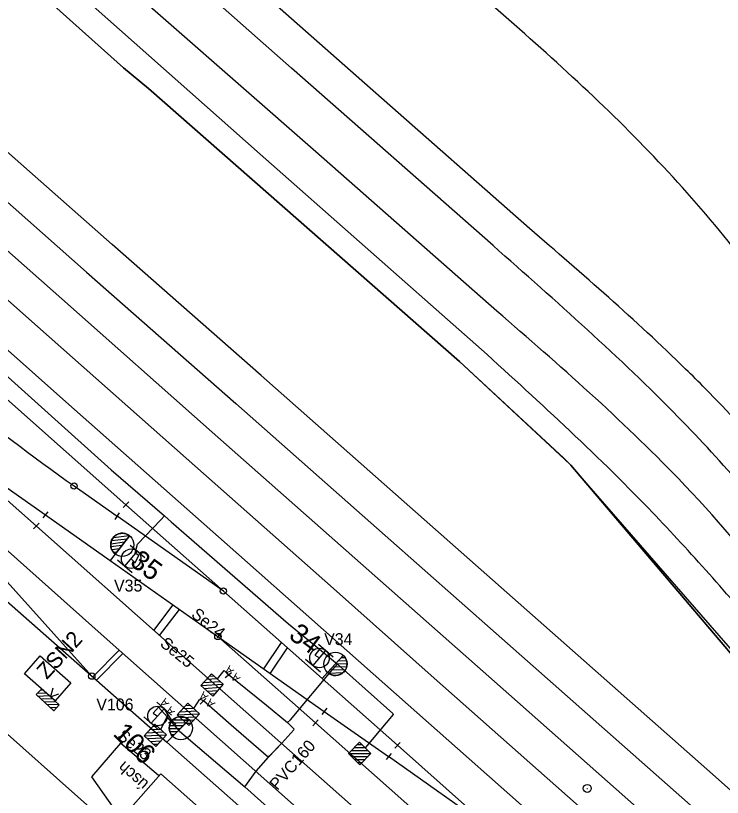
# Model space of a CAD drawing. Extents: x -496570 to -495506, y -1089156 to -1088046.
# Drawn here: x -496185.7 to -496096.7, y -1088491.2 to -1088392.7 of the extents above; entities that cross this region are included whole.
import ezdxf

# ---------------------------------------------------------------- set-up
doc = ezdxf.new("R2010")
doc.units = 0
for name, color, linetype in [('11', 7, 'Continuous'), ('14', 7, 'Continuous'), ('15', 7, 'Continuous'), ('20', 7, 'Continuous'), ('27', 7, 'Continuous'), ('39', 7, 'Continuous'), ('54', 7, 'Continuous'), ('PŘÍSTUPOVÉ_CESTY', 7, 'Continuous'), ('PŮVODNÍ_NÁVRH', 7, 'Continuous'), ('SEE', 7, 'Continuous')]:
    doc.layers.add(name, color=color, linetype=linetype)

msp = doc.modelspace()

# ---------------------------------------------------------------- linework, layer by layer
at = {"layer": '11'}
for p, q in [((-496175.966, -1088476.01), (-496172.647, -1088472.653)), ((-496175.563, -1088476.455), (-496172.198, -1088473.051)), ((-496113.753, -1088490.122), (-496113.653, -1088490.122))]:
    msp.add_line(p, q, dxfattribs=at)
for points in [[(-496168.336, -1088470.189), (-496165.878, -1088466.959)], [(-496167.583, -1088470.852), (-496165.082, -1088467.565)], [(-496154.451, -1088475.041), (-496152.237, -1088471.722)], [(-496153.619, -1088475.595), (-496151.481, -1088472.391)]]:
    msp.add_lwpolyline(points, dxfattribs=at)
msp.add_circle((-496113.703, -1088490.122), 0.5, dxfattribs=at)
at = {"layer": '14'}
for p, q in [((-496178.376, -1088451.975), (-496172.957, -1088455.79)), ((-496181.983, -1088455.616), (-496173.824, -1088461.376)), ((-496137.6, -1088484.685), (-496147.124, -1088476.255)), ((-496146.847, -1088480.405), (-496138.739, -1088486.107))]:
    msp.add_line(p, q, dxfattribs=at)
for points in [[(-496500.326, -1088150.883), (-496478.319, -1088170.391), (-496459.205, -1088187.309), (-496440.603, -1088203.768), (-496419.398, -1088222.532), (-496401.337, -1088238.524), (-496381.863, -1088255.763), (-496363.496, -1088272.022), (-496344.908, -1088288.479), (-496325.602, -1088305.577), (-496305.115, -1088323.698), (-496285.279, -1088341.274), (-496267.778, -1088356.78), (-496248.642, -1088373.733), (-496220.391, -1088398.759), (-496201.351, -1088415.62), (-496182.974, -1088431.889), (-496164.259, -1088448.462), (-496145.687, -1088464.902), (-496132.984, -1088476.226), (-496115.09, -1088492.058), (-496092.682, -1088511.89), (-496073.961, -1088528.378)], [(-496111.45, -1088501.61), (-496112.796, -1088500.414), (-496116.847, -1088496.777), (-496137.726, -1088478.277), (-496158.004, -1088460.314), (-496179.39, -1088441.364), (-496198.571, -1088424.361), (-496223.52, -1088402.267), (-496247.329, -1088381.198), (-496269.626, -1088361.454), (-496288.304, -1088344.927), (-496319.947, -1088316.905), (-496344.485, -1088295.207), (-496348.139, -1088291.966), (-496366.841, -1088275.405), (-496385.169, -1088259.187), (-496404.395, -1088242.153), (-496422.154, -1088226.434), (-496443.818, -1088207.26), (-496462.548, -1088190.678), (-496481.576, -1088173.849), (-496503.417, -1088154.088)], [(-496036.118, -1088555.5), (-496048.975, -1088544.1), (-496066.196, -1088528.906), (-496086.152, -1088511.349), (-496104.929, -1088494.746), (-496123.588, -1088478.229), (-496142.293, -1088461.701), (-496160.965, -1088445.175), (-496179.891, -1088428.396), (-496198.214, -1088412.189), (-496217.292, -1088395.311), (-496245.811, -1088370.064), (-496264.918, -1088353.145), (-496281.988, -1088338.018), (-496302.247, -1088320.079), (-496322.57, -1088302.076), (-496341.966, -1088284.907), (-496360.552, -1088268.447), (-496378.713, -1088252.378), (-496398.4, -1088234.928), (-496416.447, -1088218.945), (-496437.668, -1088200.162), (-496456.103, -1088183.845), (-496474.042, -1088168.071)], [(-496082.486, -1088502.043), (-496098.63, -1088487.696), (-496117.358, -1088471.138), (-496136.056, -1088454.602), (-496154.785, -1088438.063), (-496173.551, -1088421.521), (-496192.303, -1088405.013), (-496211.05, -1088388.494), (-496229.814, -1088371.969), (-496241.71, -1088361.483), (-496259.312, -1088345.98), (-496335.952, -1088278.18), (-496354.664, -1088261.608), (-496372.853, -1088245.502), (-496392.083, -1088228.459), (-496410.817, -1088211.882), (-496431.795, -1088193.31), (-496448.334, -1088178.663)], [(-496419.776, -1088210.17), (-496413.73, -1088215.561), (-496395.384, -1088231.799), (-496375.938, -1088249.024), (-496357.661, -1088265.193), (-496339.088, -1088281.642), (-496320.817, -1088297.785), (-496278.447, -1088335.251), (-496262.212, -1088349.594), (-496242.734, -1088366.795), (-496214.147, -1088392.048), (-496195.339, -1088408.643), (-496176.8, -1088425.002), (-496157.997, -1088441.59), (-496139.148, -1088458.239), (-496120.509, -1088474.69), (-496101.775, -1088491.246), (-496088.913, -1088502.664), (-496081.326, -1088509.353), (-496072.768, -1088516.905)], [(-496120.979, -1088419.513), (-496140.339, -1088402.432), (-496221.525, -1088330.811), (-496231.876, -1088321.658)], [(-496125.575, -1088421.675), (-496150.959, -1088399.291), (-496155.261, -1088395.496), (-496219.317, -1088338.861)], [(-496125.082, -1088429.936), (-496147.897, -1088409.846), (-496175.915, -1088385.245), (-496200.868, -1088363.307), (-496213.622, -1088352.053), (-496223.062, -1088343.696)], [(-496128.434, -1088433.508), (-496154.903, -1088410.124), (-496191.894, -1088377.361), (-496213.869, -1088358.021), (-496226.145, -1088347.189)], [(-496174.593, -1088471.013), (-496192.559, -1088454.988), (-496206.347, -1088442.759), (-496213.463, -1088436.447), (-496216.342, -1088433.89), (-496225.123, -1088426.139), (-496237.731, -1088415.01), (-496248.348, -1088406.17), (-496261.601, -1088395.991)], [(-496235.541, -1088397.911), (-496201.57, -1088427.952), (-496171.826, -1088454.349)], [(-496183.115, -1088457.032), (-496166.27, -1088472.019), (-496131.046, -1088503.215), (-496098.048, -1088532.397), (-496093.805, -1088536.044)], [(-496093.621, -1088542.853), (-496114.06, -1088524.717), (-496138.8, -1088502.766), (-496174.593, -1088471.013)], [(-496173.425, -1088495.115), (-496178.653, -1088490.5), (-496194.892, -1088476.055)], [(-496147.947, -1088481.853), (-496126.772, -1088500.653), (-496102.22, -1088522.373)], [(-496104.138, -1088539.66), (-496119.75, -1088525.847), (-496148.539, -1088500.347), (-496166.679, -1088484.292)]]:
    msp.add_lwpolyline(points, dxfattribs=at)
msp.add_circle((-496178.376, -1088451.975), 0.4, dxfattribs=at)
msp.add_ellipse((-495933.646, -1088110.004), major_axis=(-336.539, 253.741), ratio=0.997726, start_param=1.503783, end_param=1.595629, dxfattribs=at)
for points in [[(-496074.283, -1088455.273), (-496090.055, -1088428.91), (-496108.418, -1088407.261), (-496129.685, -1088387.877)], [(-496060.305, -1088494.392), (-496069.107, -1088478.342), (-496082.819, -1088457.845), (-496098.833, -1088439.695), (-496101.304, -1088437.234), (-496120.979, -1088419.513)], [(-496072.447, -1088480.385), (-496086.263, -1088461.553), (-496102.223, -1088443.302), (-496125.575, -1088421.675)], [(-496074.345, -1088485.622), (-496089.123, -1088466.132), (-496102.218, -1088451.049), (-496125.082, -1088429.936)], [(-496077.528, -1088487.052), (-496084.13, -1088479.499), (-496092.21, -1088470.077), (-496106.458, -1088454.308), (-496128.434, -1088433.508)]]:
    msp.add_spline(points, degree=3, dxfattribs=at)
at = {"layer": '15'}
for p, q in [((-496171.312, -1088459.424), (-496169.434, -1088461.018)), ((-496171.967, -1088462.099), (-496170.373, -1088460.221)), ((-496172.906, -1088461.302), (-496171.028, -1088462.896)), ((-496147.582, -1088471.933), (-496145.713, -1088473.538)), ((-496148.253, -1088474.605), (-496146.647, -1088472.735)), ((-496149.187, -1088473.802), (-496147.318, -1088475.407)), ((-496161.681, -1088476.352), (-496160.356, -1088476.27)), ((-496161.33, -1088475.955), (-496160.753, -1088475.919)), ((-496162.383, -1088477.148), (-496159.56, -1088476.972)), ((-496162.033, -1088476.75), (-496159.958, -1088476.621)), ((-496161.986, -1088477.498), (-496159.911, -1088477.369)), ((-496161.588, -1088477.85), (-496160.262, -1088477.767)), ((-496161.191, -1088478.2), (-496160.613, -1088478.165)), ((-496167.95, -1088479.251), (-496166.111, -1088480.89)), ((-496168.67, -1088481.91), (-496167.03, -1088480.07)), ((-496164.662, -1088480.054), (-496163.335, -1088479.989)), ((-496164.306, -1088479.661), (-496163.728, -1088479.633)), ((-496169.589, -1088481.09), (-496167.75, -1088482.729)), ((-496165.374, -1088480.84), (-496162.549, -1088480.702)), ((-496165.018, -1088480.447), (-496162.942, -1088480.346)), ((-496164.982, -1088481.196), (-496162.905, -1088481.094)), ((-496168.464, -1088482.306), (-496167.886, -1088482.281)), ((-496164.588, -1088481.553), (-496163.262, -1088481.488)), ((-496164.196, -1088481.909), (-496163.618, -1088481.88)), ((-496169.18, -1088483.089), (-496167.103, -1088482.997)), ((-496168.822, -1088482.697), (-496167.495, -1088482.639)), ((-496169.538, -1088483.479), (-496166.713, -1088483.355)), ((-496169.147, -1088483.837), (-496167.071, -1088483.746)), ((-496168.756, -1088484.196), (-496167.429, -1088484.138)), ((-496168.365, -1088484.554), (-496167.787, -1088484.529)), ((-496143.041, -1088484.968), (-496141.713, -1088484.957)), ((-496142.67, -1088484.59), (-496142.091, -1088484.586)), ((-496143.785, -1088485.725), (-496140.957, -1088485.701)), ((-496143.414, -1088485.347), (-496141.335, -1088485.33)), ((-496143.407, -1088486.097), (-496141.329, -1088486.079)), ((-496143.029, -1088486.469), (-496141.701, -1088486.458)), ((-496142.651, -1088486.84), (-496142.072, -1088486.836))]:
    msp.add_line(p, q, dxfattribs=at)
for points in [[(-496161.06, -1088475.648), (-496159.56, -1088476.972), (-496160.884, -1088478.471), (-496162.383, -1088477.148)], [(-496161.06, -1088475.648), (-496159.56, -1088476.972), (-496160.884, -1088478.471), (-496162.383, -1088477.148)], [(-496164.031, -1088479.358), (-496162.549, -1088480.702), (-496163.893, -1088482.183), (-496165.374, -1088480.84)], [(-496164.031, -1088479.358), (-496162.549, -1088480.702), (-496163.893, -1088482.183), (-496165.374, -1088480.84)], [(-496168.187, -1088482.005), (-496166.713, -1088483.355), (-496168.063, -1088484.83), (-496169.538, -1088483.479)], [(-496168.187, -1088482.005), (-496166.713, -1088483.355), (-496168.063, -1088484.83), (-496169.538, -1088483.479)], [(-496142.383, -1088484.299), (-496140.957, -1088485.701), (-496142.359, -1088487.127), (-496143.785, -1088485.725)], [(-496142.383, -1088484.299), (-496140.957, -1088485.701), (-496142.359, -1088487.127), (-496143.785, -1088485.725)]]:
    msp.add_lwpolyline(points, close=True, dxfattribs=at)
for points in [[(-496161.06, -1088475.648), (-496159.56, -1088476.972), (-496160.884, -1088478.471), (-496162.383, -1088477.148), (-496161.06, -1088475.648)], [(-496161.06, -1088475.648), (-496159.56, -1088476.972), (-496160.884, -1088478.471), (-496162.383, -1088477.148), (-496161.06, -1088475.648)], [(-496164.031, -1088479.358), (-496162.549, -1088480.702), (-496163.893, -1088482.183), (-496165.374, -1088480.84), (-496164.031, -1088479.358)], [(-496164.031, -1088479.358), (-496162.549, -1088480.702), (-496163.893, -1088482.183), (-496165.374, -1088480.84), (-496164.031, -1088479.358)], [(-496168.187, -1088482.005), (-496166.713, -1088483.355), (-496168.063, -1088484.83), (-496169.538, -1088483.479), (-496168.187, -1088482.005)], [(-496168.187, -1088482.005), (-496166.713, -1088483.355), (-496168.063, -1088484.83), (-496169.538, -1088483.479), (-496168.187, -1088482.005)], [(-496142.383, -1088484.299), (-496140.957, -1088485.701), (-496142.359, -1088487.127), (-496143.785, -1088485.725), (-496142.383, -1088484.299)], [(-496142.383, -1088484.299), (-496140.957, -1088485.701), (-496142.359, -1088487.127), (-496143.785, -1088485.725), (-496142.383, -1088484.299)]]:
    msp.add_lwpolyline(points, dxfattribs=at)
for centre in [(-496171.168, -1088461.155), (-496147.448, -1088473.665), (-496167.848, -1088480.986)]:
    msp.add_circle(centre, 1.232, dxfattribs=at)
at = {"layer": '20'}
for p, q in [((-496158.548, -1088475.526), (-496159.308, -1088476.174)), ((-496161.763, -1088478.788), (-496162.483, -1088479.482)), ((-496167.155, -1088479.93), (-496166.06, -1088481.58)), ((-496166.477, -1088481.857), (-496165.643, -1088481.303))]:
    msp.add_line(p, q, dxfattribs=at)
at = {"layer": '27'}
for p, q in [((-496171.474, -1088453.994), (-496172.178, -1088454.704)), ((-496181.669, -1088455.227), (-496182.297, -1088456.005)), ((-496172.69, -1088455.367), (-496173.224, -1088456.213)), ((-496182.768, -1088456.672), (-496183.462, -1088457.392)), ((-496173.659, -1088458.874), (-496171.692, -1088458.624)), ((-496173.421, -1088458.47), (-496171.429, -1088458.218)), ((-496171.403, -1088458.247), (-496173.195, -1088460.561)), ((-496171.396, -1088458.242), (-496173.189, -1088460.555)), ((-496172.762, -1088458.014), (-496172.175, -1088457.94)), ((-496171.397, -1088458.241), (-496171.396, -1088458.242)), ((-496173.748, -1088459.258), (-496172.013, -1088459.038)), ((-496173.734, -1088459.629), (-496172.334, -1088459.451)), ((-496173.197, -1088460.561), (-496173.824, -1088461.376)), ((-496173.627, -1088459.989), (-496172.654, -1088459.865)), ((-496173.413, -1088460.334), (-496172.975, -1088460.279)), ((-496146.428, -1088475.497), (-496144.442, -1088473.347)), ((-496144.442, -1088473.347), (-496146.427, -1088475.498)), ((-496145.419, -1088474.406), (-496143.976, -1088474.349)), ((-496145.06, -1088474.017), (-496144.045, -1088473.976)), ((-496144.699, -1088473.627), (-496144.223, -1088473.608)), ((-496146.14, -1088475.185), (-496144.143, -1088475.105)), ((-496145.78, -1088474.795), (-496144.005, -1088474.725)), ((-496146.429, -1088475.498), (-496147.124, -1088476.255)), ((-496146.427, -1088475.498), (-496146.428, -1088475.497)), ((-496146.34, -1088475.568), (-496144.443, -1088475.493)), ((-496146.537, -1088480.012), (-496147.157, -1088480.798)), ((-496165.21, -1088481.087), (-496164.619, -1088481.085)), ((-496166.342, -1088482.199), (-496164.594, -1088482.195)), ((-496166.207, -1088481.829), (-496164.224, -1088481.824)), ((-496163.891, -1088481.486), (-496165.955, -1088483.561)), ((-496163.883, -1088481.481), (-496165.948, -1088483.555)), ((-496165.921, -1088481.458), (-496163.913, -1088481.453)), ((-496163.884, -1088481.48), (-496163.883, -1088481.481)), ((-496147.604, -1088481.489), (-496148.29, -1088482.217)), ((-496166.375, -1088482.569), (-496164.963, -1088482.566)), ((-496166.313, -1088482.94), (-496165.332, -1088482.936)), ((-496165.956, -1088483.561), (-496166.679, -1088484.292)), ((-496166.143, -1088483.309), (-496165.702, -1088483.308)), ((-496137.261, -1088484.318), (-496137.939, -1088485.052)), ((-496138.42, -1088485.722), (-496139.058, -1088486.492))]:
    msp.add_line(p, q, dxfattribs=at)
for points in [[(-496183.115, -1088457.032), (-496195.371, -1088446.182), (-496207.812, -1088435.168)], [(-496195.371, -1088446.182), (-496181.983, -1088455.616)], [(-496147.124, -1088476.255), (-496159.556, -1088465.23), (-496171.826, -1088454.349)], [(-496159.556, -1088465.23), (-496172.957, -1088455.79)], [(-496173.824, -1088461.376), (-496160.246, -1088470.954), (-496146.847, -1088480.405)], [(-496176.139, -1088475.956), (-496187.184, -1088463.633)], [(-496187.97, -1088465.532), (-496166.679, -1088484.292)], [(-496160.246, -1088470.954), (-496147.947, -1088481.853)], [(-496112.903, -1088506.6), (-496125.331, -1088495.572), (-496137.6, -1088484.685)], [(-496125.331, -1088495.572), (-496138.739, -1088486.107)]]:
    msp.add_lwpolyline(points, dxfattribs=at)
for centre, radius in [((-496172.293, -1088459.399), 1.462), ((-496159.556, -1088465.23), 0.4), ((-496160.246, -1088470.954), 0.4), ((-496145.428, -1088474.417), 1.462), ((-496176.139, -1088475.956), 0.4), ((-496164.916, -1088482.518), 1.462)]:
    msp.add_circle(centre, radius, dxfattribs=at)
for centre, start, end in [((-496172.292, -1088459.398), 52.25556, 232.21641), ((-496145.435, -1088474.422), 227.29698, 47.25783), ((-496164.915, -1088482.518), 45.17373, 225.13458)]:
    msp.add_arc(centre, 1.464, start, end, dxfattribs=at)
at = {"layer": '39'}
for points in [[(-496182.631, -1088473.407), (-496178.781, -1088476.82), (-496180.757, -1088479.091), (-496184.629, -1088475.67), (-496182.631, -1088473.407)], [(-496172.423, -1088493.891), (-496176.128, -1088488.669), (-496172.468, -1088484.41), (-496167.748, -1088488.466)], [(-496122.209, -1088528.323), (-496134.209, -1088541.938), (-496150.053, -1088527.973), (-496152.367, -1088530.599), (-496181.619, -1088504.378), (-496167.429, -1088488.299), (-496122.209, -1088528.323)]]:
    msp.add_lwpolyline(points, dxfattribs=at)
at = {"layer": '54'}
for p, q in [((-496159.11, -1088475.58), (-496158.928, -1088475.85)), ((-496162.06, -1088479.04), (-496162.123, -1088479.135))]:
    msp.add_line(p, q, dxfattribs=at)
for points in [[(-496093.74, -1088475.27), (-496115.78, -1088449.34), (-496116.666, -1088448.476), (-496129.8, -1088436.28), (-496168.994, -1088401.872), (-496172.14, -1088399.257), (-496208.919, -1088366.316), (-496218.168, -1088358.05), (-496219.89, -1088357.07), (-496220.84, -1088356.616), (-496221.139, -1088356.856), (-496221.818, -1088357.316), (-496227.949, -1088364.044), (-496231.283, -1088367.587), (-496235.293, -1088372.311), (-496239.162, -1088376.183), (-496245.965, -1088384.343), (-496248.122, -1088386.702), (-496249.196, -1088385.882), (-496252.528, -1088385.701), (-496270.673, -1088369.666)], [(-496035.05, -1088546.1), (-496051.31, -1088524.79), (-496051.95, -1088524), (-496075.46, -1088495.01), (-496082.21, -1088487.56), (-496083.74, -1088486.13), (-496115.78, -1088449.34), (-496116.666, -1088448.476), (-496129.8, -1088436.28), (-496168.994, -1088401.872), (-496172.14, -1088399.257), (-496208.919, -1088366.316), (-496218.168, -1088358.05), (-496219.89, -1088357.07), (-496221.818, -1088357.316), (-496227.949, -1088364.044), (-496231.283, -1088367.587), (-496235.293, -1088372.311), (-496239.162, -1088376.183), (-496245.965, -1088384.343), (-496248.182, -1088386.654), (-496249.196, -1088385.882), (-496252.528, -1088385.701), (-496270.673, -1088369.666)], [(-496249.196, -1088385.882), (-496248.182, -1088386.654), (-496245.965, -1088384.343), (-496239.162, -1088376.183), (-496235.293, -1088372.311), (-496231.283, -1088367.587), (-496227.949, -1088364.044), (-496221.818, -1088357.316), (-496219.9, -1088357.08), (-496218.168, -1088358.05), (-496208.919, -1088366.316), (-496172.14, -1088399.257), (-496168.994, -1088401.872), (-496129.8, -1088436.28), (-496116.666, -1088448.476), (-496115.78, -1088449.34), (-496093.74, -1088475.27), (-496082.49, -1088487.89), (-496075.35, -1088495.41), (-496051.95, -1088524), (-496051.31, -1088524.79), (-496034.93, -1088546.87)], [(-496240.55, -1088394.77), (-496237.99, -1088397.05), (-496235.53, -1088394.7), (-496226.92, -1088402.46), (-496217.51, -1088410.88), (-496206.66, -1088420.23), (-496201.26, -1088425.11), (-496190.86, -1088434.52), (-496173.69, -1088449.93), (-496166.99, -1088455.74), (-496166.15, -1088456.51), (-496151.36, -1088469.35), (-496147.46, -1088472.55), (-496145.16, -1088474.43), (-496138.22, -1088480.69), (-496138.14, -1088480.81), (-496141.67, -1088485)], [(-496171.17, -1088461.16), (-496170.65, -1088461.67), (-496170.63, -1088461.55), (-496170.21, -1088460.73), (-496170.66, -1088460.45), (-496170.39, -1088459.33), (-496167.42, -1088456.25), (-496166.99, -1088455.74)], [(-496147.46, -1088472.55), (-496148.05, -1088473.3), (-496147.45, -1088473.67)], [(-496160.31, -1088476.31), (-496159.44, -1088475.23), (-496159.11, -1088475.58), (-496154.14, -1088479.61), (-496151.49, -1088481.8)], [(-496156.87, -1088489.91), (-496155.41, -1088487.95), (-496153.88, -1088486.17), (-496153.76, -1088486.02), (-496152.18, -1088484.43), (-496150.69, -1088482.73), (-496150.62, -1088482.66), (-496151.49, -1088481.8), (-496151.11, -1088481.48), (-496145.76, -1088475.09), (-496145.16, -1088474.43)], [(-496163.29, -1088480.03), (-496162.53, -1088478.85), (-496162.06, -1088479.04), (-496158.57, -1088482.12), (-496153.88, -1088486.17), (-496153.76, -1088486.02)], [(-496165.07, -1088482.9), (-496165.721, -1088482.151), (-496166.63, -1088481.104), (-496167.71, -1088479.86), (-496168.42, -1088480.61), (-496167.85, -1088480.99)], [(-496167.45, -1088482.68), (-496166.66, -1088481.14), (-496166.63, -1088481.104)], [(-496166.06, -1088481.58), (-496165.53, -1088481.99), (-496165.721, -1088482.151)], [(-496165.07, -1088482.9), (-496156.87, -1088489.91), (-496145.17, -1088500.37), (-496132.17, -1088511.64), (-496132.14, -1088511.95), (-496109.93, -1088531.36), (-496085.16, -1088553.21), (-496080.73, -1088556.99), (-496073.59, -1088563.01), (-496067.7, -1088567.42), (-496060.271, -1088572.567), (-496056.99, -1088574.85), (-496054.978, -1088576.218), (-496044.9, -1088583.07), (-496037.32, -1088587.86), (-496035.7, -1088586.08), (-496034.22, -1088583.93), (-496031.57, -1088584.92), (-496029.17, -1088586.56)]]:
    msp.add_lwpolyline(points, dxfattribs=at)
at = {"layer": 'PŘÍSTUPOVÉ_CESTY'}
for p, q in [((-496182.959, -1088478.093), (-496181.902, -1088478.056)), ((-496182.598, -1088477.705), (-496182.29, -1088477.694)), ((-496182.927, -1088478.467), (-496181.514, -1088478.418)), ((-496182.539, -1088478.829), (-496181.126, -1088478.779)), ((-496182.152, -1088479.19), (-496180.738, -1088479.14)), ((-496181.763, -1088479.552), (-496180.35, -1088479.502)), ((-496181.375, -1088479.913), (-496180.527, -1088479.883)), ((-496180.988, -1088480.275), (-496180.889, -1088480.271))]:
    msp.add_line(p, q, dxfattribs=at)
msp.add_lwpolyline([(-496182.45, -1088477.546), (-496180.255, -1088479.591), (-496180.936, -1088480.322), (-496183.131, -1088478.277)], close=True, dxfattribs=at)
for points in [[(-496182.45, -1088477.546), (-496180.255, -1088479.591), (-496180.936, -1088480.322), (-496183.131, -1088478.277), (-496182.45, -1088477.546)], [(-496181.036, -1088477.496), (-496181.352, -1088478.568), (-496180.305, -1088478.177)]]:
    msp.add_lwpolyline(points, dxfattribs=at)
at = {"layer": 'PŮVODNÍ_NÁVRH'}
for p, q in [((-496170.39, -1088459.33), (-496167.42, -1088456.25)), ((-496151.11, -1088481.48), (-496145.76, -1088475.09))]:
    msp.add_line(p, q, dxfattribs=at)
for points in [[(-496115.78, -1088449.34), (-496116.57, -1088448.6), (-496129.8, -1088436.28), (-496168.994, -1088401.872), (-496172.14, -1088399.257), (-496208.919, -1088366.316), (-496218.168, -1088358.05), (-496219.89, -1088357.07), (-496220.839, -1088356.597)], [(-496015.829, -1088567.72), (-496024.83, -1088557.73), (-496034.93, -1088546.87), (-496051.31, -1088524.79), (-496051.95, -1088524), (-496075.35, -1088495.41), (-496082.21, -1088487.56), (-496083.78, -1088486.19), (-496093.74, -1088475.27), (-496115.78, -1088449.34)], [(-496156.87, -1088489.91), (-496155.41, -1088487.95), (-496153.88, -1088486.17), (-496152.18, -1088484.43), (-496150.69, -1088482.73)]]:
    msp.add_lwpolyline(points, dxfattribs=at)
at = {"layer": 'SEE'}
msp.add_lwpolyline([(-496270.673, -1088369.666), (-496252.528, -1088385.701), (-496249.196, -1088385.882), (-496248.122, -1088386.702), (-496239.162, -1088376.183), (-496235.293, -1088372.311), (-496231.283, -1088367.587), (-496227.949, -1088364.044), (-496221.818, -1088357.316), (-496221.075, -1088356.805), (-496220.84, -1088356.616), (-496219.9, -1088357.08), (-496218.168, -1088358.05), (-496208.919, -1088366.316), (-496172.14, -1088399.257), (-496168.994, -1088401.872), (-496129.8, -1088436.28), (-496116.666, -1088448.476), (-496115.78, -1088449.34), (-496093.74, -1088475.27)], dxfattribs=at)
msp.add_lwpolyline([(-496270.673, -1088369.666), (-496252.528, -1088385.701), (-496249.196, -1088385.882), (-496248.122, -1088386.702), (-496239.162, -1088376.183), (-496235.293, -1088372.311), (-496231.283, -1088367.587), (-496227.949, -1088364.044), (-496221.818, -1088357.316), (-496221.075, -1088356.805), (-496220.84, -1088356.616), (-496219.9, -1088357.08), (-496218.168, -1088358.05), (-496208.919, -1088366.316), (-496172.14, -1088399.257), (-496168.994, -1088401.872), (-496129.8, -1088436.28), (-496116.666, -1088448.476), (-496115.78, -1088449.34), (-496093.74, -1088475.27)], dxfattribs=at)

# ---------------------------------------------------------------- texts
at = {"layer": '15'}
for s, p in [('V35', (-496173.333, -1088465.29)), ('V34', (-496146.856, -1088472.042)), ('V106', (-496175.562, -1088480.28))]:
    msp.add_text(s, height=1.5, dxfattribs=at).set_placement(p)
at = {"layer": '20'}
for s, height, rotation, p in [('Se24', 1.5, 320.6127, (-496163.715, -1088468.378)), ('Se25', 1.5, 320.6127, (-496167.65, -1088472.043)), ('  A A', 1, 130.45324, (-496156.871, -1088476.748)), ('  A A', 1, 133.87204, (-496160.016, -1088479.908)), ('  A A', 1, 123.57393, (-496165.225, -1088481.077)), ('Se23', 1.5, 320.6127, (-496173.05, -1088483.705))]:
    msp.add_text(s, height=height, rotation=rotation, dxfattribs=at).set_placement(p)
at = {"layer": '27'}
for s, rotation, p in [('35', 323.28202, (-496171.468, -1088461.854)), ('34', 323.28202, (-496151.456, -1088471.088)), ('106', 315.15416, (-496173.576, -1088483.336))]:
    msp.add_text(s, height=2.5, rotation=rotation, dxfattribs=at).set_placement(p)
at = {"layer": '39'}
msp.add_text('úsch', height=1.5, rotation=138.53867, dxfattribs=at).set_placement((-496168.866, -1088489.394))
at = {"layer": '54'}
msp.add_text('PVC160', height=1.5, rotation=48.83062, dxfattribs=at).set_placement((-496152.757, -1088490.446))
at = {"layer": 'PŘÍSTUPOVÉ_CESTY'}
msp.add_text('ZSN2', height=2, rotation=47.48221, dxfattribs=at).set_placement((-496181.792, -1088476.465))

doc.saveas('drawing.dxf')
